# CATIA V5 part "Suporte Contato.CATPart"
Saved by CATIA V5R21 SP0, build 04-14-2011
Part number: Suporte Contato
Definition: Suporte Contato
Nomenclature: Suporte Contato
Source: Unknown
Bounding box of the stored display mesh (mm): x -0.988 to 0.988, y -2.8 to 0.2, z -1.1 to 0.7
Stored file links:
  C:\Users\beatr\OneDrive\Documents\UNB\2026_1\Pi1\Componentes eletronicos\Suporte Contato.CATPart
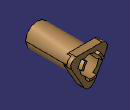
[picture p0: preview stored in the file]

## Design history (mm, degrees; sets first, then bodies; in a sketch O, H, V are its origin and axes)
Body1 "Sólido1" (main body)
  Solid1: solid without history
